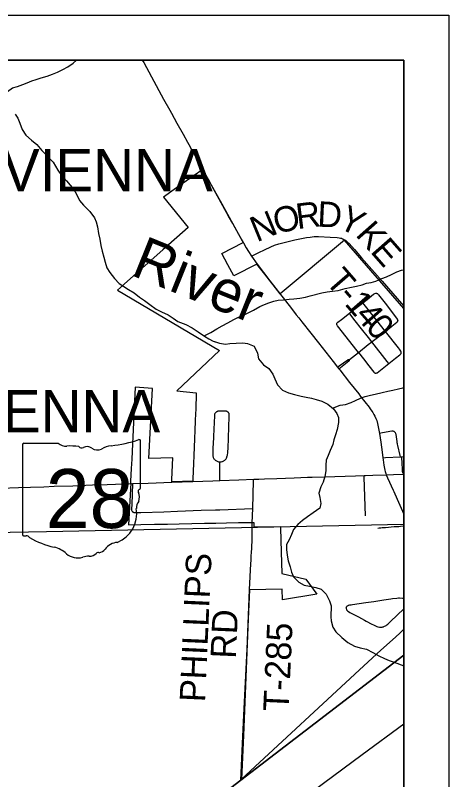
# Model space of a CAD drawing. Extents: x 0 to 48.6, y 0 to 22.
# Drawn here: x 8.031 to 9, y 19.291 to 21 of the extents above; entities that cross this region are included whole.
import ezdxf

# ---------------------------------------------------------------- set-up
doc = ezdxf.new("R2010")
doc.units = 0
for name, color, linetype in [('GM_X_City_Street', 7, 'Continuous'), ('GM_X_Corporation', 7, 'Continuous'), ('GM_X_Corporation_Text', 7, 'Continuous'), ('GM_X_Major_River', 7, 'Continuous'), ('GM_X_Major_River_Text', 7, 'Continuous'), ('GM_X_Minor_River', 7, 'Continuous'), ('GM_X_Rail_Line', 7, 'Continuous'), ('GM_X_State_Location', 7, 'Continuous'), ('GM_X_State_Route', 7, 'Continuous'), ('GM_X_State_Shield', 7, 'Continuous'), ('GM_X_Township_Road', 7, 'Continuous'), ('GM_X_Township_Road_Text', 7, 'Continuous'), ('SH_Data', 7, 'Continuous')]:
    doc.layers.add(name, color=color, linetype=linetype)

msp = doc.modelspace()

# ---------------------------------------------------------------- linework, layer by layer
at = {"layer": 'GM_X_City_Street'}
for points in [[(8.7982, 20.2463), (8.7953, 20.25), (8.7512, 20.3058), (8.7504, 20.307), (8.75, 20.3079), (8.7498, 20.3091), (8.7497, 20.3104), (8.75, 20.3114), (8.7506, 20.3124), (8.7521, 20.3141), (8.7601, 20.3199), (8.7781, 20.3338), (8.7837, 20.3381), (8.7919, 20.3447), (8.8079, 20.3571), (8.8174, 20.3645), (8.832, 20.3761), (8.835, 20.3779), (8.8367, 20.3784), (8.8377, 20.3784), (8.8384, 20.3784), (8.8396, 20.378), (8.8405, 20.3775), (8.8412, 20.3769), (8.8422, 20.3758), (8.8431, 20.3747), (8.8578, 20.356), (8.8746, 20.3345), (8.885, 20.3204), (8.8855, 20.3196), (8.8858, 20.3189), (8.886, 20.3183), (8.8861, 20.3173)], [(8.7982, 20.2463), (8.8093, 20.2319), (8.8214, 20.2162), (8.8325, 20.2023), (8.8335, 20.2012), (8.8343, 20.2005), (8.835, 20.2001), (8.8356, 20.1998), (8.8365, 20.1996), (8.838, 20.1998), (8.8391, 20.2002), (8.8399, 20.2008), (8.866, 20.2212), (8.8813, 20.2331), (8.8904, 20.2404), (8.8913, 20.2412), (8.8922, 20.242), (8.8929, 20.243), (8.8934, 20.244), (8.8937, 20.2456), (8.8935, 20.2472), (8.8929, 20.2487), (8.8916, 20.2508), (8.8896, 20.2537), (8.8874, 20.2565), (8.8586, 20.2931), (8.839, 20.3178), (8.8136, 20.3499), (8.8079, 20.3571)], [(8.866, 20.2212), (8.8624, 20.2259), (8.828, 20.2701), (8.8206, 20.2796), (8.8052, 20.2991), (8.7909, 20.3171), (8.7814, 20.3294), (8.7781, 20.3338)], [(8.7782, 20.2303), (8.7982, 20.2463), (8.8196, 20.2635), (8.828, 20.2701), (8.8289, 20.2707), (8.8526, 20.2887), (8.8586, 20.2931), (8.8731, 20.3048), (8.8841, 20.3137), (8.8852, 20.3148), (8.8857, 20.3154), (8.8859, 20.3161), (8.8861, 20.3173)], [(8.7515, 20.2133), (8.7553, 20.2161), (8.7742, 20.2299), (8.7748, 20.2302), (8.7756, 20.2304), (8.7767, 20.2306), (8.7782, 20.2303)], [(8.7545, 20.2095), (8.758, 20.2122), (8.777, 20.227), (8.7775, 20.2276), (8.7779, 20.2282), (8.7782, 20.2289), (8.7782, 20.2303)], [(8.4881, 19.9598), (8.4881, 19.9626), (8.4883, 20.0012), (8.4912, 20.0016), (8.4931, 20.0021), (8.4939, 20.0024), (8.4954, 20.0031), (8.4968, 20.0038), (8.4981, 20.0046), (8.499, 20.0052), (8.4998, 20.0059), (8.5007, 20.0066), (8.5014, 20.0073), (8.5021, 20.0083), (8.5028, 20.0094), (8.5033, 20.0102), (8.5038, 20.0115), (8.5042, 20.0124), (8.5048, 20.0147), (8.5053, 20.0165), (8.5056, 20.0182), (8.506, 20.0209), (8.5061, 20.0227), (8.5063, 20.0249), (8.5066, 20.0316), (8.5092, 20.1031), (8.5092, 20.1041), (8.5092, 20.1051), (8.5092, 20.1061), (8.509, 20.1075), (8.5087, 20.1092), (8.5083, 20.1101), (8.508, 20.1107), (8.5077, 20.1112), (8.5072, 20.1119), (8.5067, 20.1124), (8.5057, 20.1132), (8.5051, 20.1136), (8.5044, 20.114), (8.5038, 20.1143), (8.5032, 20.1145), (8.5015, 20.1147), (8.4993, 20.1148), (8.4917, 20.1147), (8.4902, 20.1147), (8.4878, 20.1146), (8.4863, 20.1146), (8.4852, 20.1145), (8.484, 20.1144), (8.4834, 20.1143), (8.4826, 20.1141), (8.4819, 20.1138), (8.4812, 20.1135), (8.4805, 20.1131), (8.4797, 20.1125), (8.4789, 20.1118), (8.4782, 20.1112), (8.4778, 20.1106), (8.4772, 20.1098), (8.4769, 20.1092), (8.4765, 20.1084), (8.4763, 20.1077), (8.4762, 20.1067), (8.4761, 20.106), (8.476, 20.1049), (8.4753, 20.0889), (8.4747, 20.0753), (8.4739, 20.0573), (8.4732, 20.0418), (8.4727, 20.0332), (8.4725, 20.0295), (8.4724, 20.0184), (8.4725, 20.0158), (8.4727, 20.0139), (8.473, 20.0123), (8.4735, 20.011), (8.4743, 20.0095), (8.4749, 20.0085), (8.4759, 20.0073), (8.4769, 20.0063), (8.478, 20.0053), (8.4795, 20.0042), (8.4807, 20.0034), (8.4821, 20.0026), (8.4838, 20.0019), (8.4851, 20.0016), (8.4865, 20.0013), (8.4883, 20.0012)], [(8.8919, 20.0127), (8.8912, 20.0155), (8.8862, 20.0377), (8.8855, 20.0408), (8.8852, 20.0422), (8.8849, 20.0434), (8.8847, 20.0446), (8.8844, 20.0469), (8.8822, 20.0624), (8.8819, 20.064), (8.8817, 20.0651), (8.8812, 20.0661), (8.8805, 20.0672), (8.8798, 20.0681), (8.8789, 20.0688), (8.8783, 20.0692), (8.8773, 20.0696), (8.876, 20.07), (8.8749, 20.0701), (8.873, 20.0702), (8.8687, 20.0695), (8.8485, 20.0656), (8.845, 20.065)], [(8.8526, 20.0106), (8.8586, 20.0109), (8.8919, 20.0127), (8.8951, 20.0129), (8.9, 20.0131)], [(8.9, 19.9734), (8.8997, 19.9738), (8.8982, 19.9757), (8.8974, 19.9774), (8.897, 19.9792), (8.8968, 19.9817), (8.8959, 20.0015), (8.8955, 20.0081), (8.8951, 20.0129)], [(8.814, 19.881), (8.811, 19.9668), (8.8109, 19.9708)], [(8.2932, 19.9529), (8.2912, 19.906), (8.2909, 19.8966), (8.2909, 19.8949), (8.291, 19.8936), (8.2913, 19.8924), (8.2919, 19.8911), (8.2924, 19.8904), (8.2931, 19.8897), (8.2936, 19.8894), (8.2942, 19.889), (8.2948, 19.8887), (8.296, 19.8884), (8.2969, 19.8882), (8.2979, 19.888), (8.2993, 19.8879), (8.302, 19.8878), (8.3051, 19.8878), (8.3113, 19.8879), (8.3627, 19.8899), (8.3932, 19.8909), (8.4466, 19.8931), (8.4784, 19.8939), (8.4885, 19.8942), (8.5617, 19.897)], [(8.8412, 19.8531), (8.8445, 19.8536), (8.8479, 19.8541), (8.8515, 19.8543), (8.859, 19.8549), (8.8781, 19.8566), (8.8816, 19.8568), (8.8843, 19.8569), (8.8884, 19.8572), (8.8923, 19.8574), (8.8994, 19.8581), (8.9, 19.8582)], [(8.7709, 19.6749), (8.7712, 19.6764), (8.7715, 19.6771), (8.7721, 19.6782), (8.7726, 19.6787), (8.7732, 19.6793), (8.774, 19.6798), (8.775, 19.6803), (8.7757, 19.6806), (8.7768, 19.6809), (8.7787, 19.6814), (8.7799, 19.6816), (8.782, 19.682), (8.7849, 19.6824), (8.815, 19.6866), (8.8328, 19.6894), (8.8549, 19.6929), (8.8705, 19.6953), (8.8745, 19.6958), (8.8841, 19.6969), (8.8877, 19.6971), (8.8903, 19.6971), (8.8967, 19.6966), (8.8985, 19.6963), (8.9, 19.696)], [(8.7709, 19.6749), (8.7709, 19.674), (8.7709, 19.6733), (8.7711, 19.6723), (8.7714, 19.6712), (8.7718, 19.6706), (8.7724, 19.6696), (8.7736, 19.6685), (8.7758, 19.6667), (8.7791, 19.6647), (8.7833, 19.6624), (8.7939, 19.6568), (8.7982, 19.6545), (8.8115, 19.6474), (8.8152, 19.6455), (8.8281, 19.6386), (8.8317, 19.6368), (8.8364, 19.6346), (8.8391, 19.6335), (8.8418, 19.6325), (8.8456, 19.6318), (8.8477, 19.6317), (8.8497, 19.6317), (8.8512, 19.6319), (8.8525, 19.6322), (8.8539, 19.6325), (8.8551, 19.633), (8.8567, 19.6337), (8.8587, 19.6348), (8.8599, 19.6356), (8.8618, 19.637), (8.8637, 19.6387), (8.8696, 19.6443), (8.9, 19.6729)]]:
    msp.add_lwpolyline(points, dxfattribs=at)
at = {"layer": 'GM_X_Corporation'}
msp.add_lwpolyline([(6.9471, 18.0777), (7.2261, 18.2847), (8.5348, 19.2897), (8.9, 19.5692), (8.9, 20.9), (2.1, 20.9)], dxfattribs=at)
for points in [[(8.9, 19.5692), (8.9, 20.9), (5.795, 20.9), (5.8236, 20.7829), (6.0412, 19.8859), (6.2759, 18.9159), (6.3396, 18.6531), (6.4996, 17.9212), (6.5365, 17.7727), (6.9471, 18.0777), (7.2261, 18.2847), (8.5348, 19.2897)], [(8.9, 19.6269), (8.9, 20.344), (8.7669, 20.4968), (8.6233, 20.3768), (8.5885, 20.4211), (8.571, 20.4438), (8.5195, 20.4173), (8.5061, 20.4419), (8.4924, 20.467), (8.5406, 20.4918), (8.5389, 20.4948), (8.517, 20.5345), (8.5079, 20.5508), (8.4498, 20.6551), (8.4285, 20.6401), (8.3914, 20.6138), (8.3619, 20.593), (8.4171, 20.5257), (8.3605, 20.4754), (8.2815, 20.4052), (8.2662, 20.3916), (8.2594, 20.3856), (8.4875, 20.2507), (8.3918, 20.1601), (8.4352, 20.156), (8.4343, 20.118), (8.4339, 20.1104), (8.4332, 20.0921), (8.4323, 20.0726), (8.4315, 20.053), (8.4307, 20.0343), (8.4299, 20.0153), (8.4292, 19.9974), (8.4277, 19.9633), (8.4275, 19.9583), (8.3805, 19.9568), (8.3807, 19.9616), (8.3833, 20.0102), (8.3297, 20.0088), (8.3374, 20.1651), (8.2991, 20.1687), (8.2928, 20.0418), (8.2912, 20.0077), (8.2901, 19.9865), (8.2887, 19.9583), (8.2885, 19.9537), (8.2892, 19.9537), (8.2843, 19.8606), (8.3119, 19.8611), (8.3422, 19.8618), (8.3709, 19.8623), (8.3971, 19.8628), (8.4256, 19.8634), (8.4541, 19.864), (8.4793, 19.8645), (8.5028, 19.8649), (8.5296, 19.8655), (8.5565, 19.866), (8.5641, 19.8655), (8.5642, 19.8603), (8.5643, 19.8561), (8.623, 19.8572), (8.6236, 19.8528), (8.6251, 19.8005), (8.6266, 19.7514), (8.6805, 19.739), (8.7054, 19.7054), (8.6283, 19.6925), (8.6276, 19.7168), (8.5546, 19.7155), (8.5519, 19.6502), (8.5411, 19.3898), (8.537, 19.2921), (8.8103, 19.5449), (8.8483, 19.5801), (8.8741, 19.6034), (8.8897, 19.6176)], [(5.0944, 14.1), (8.9, 14.1), (8.9, 19.5692), (8.5348, 19.2897), (7.2261, 18.2847), (6.9471, 18.0777), (6.5365, 17.7727), (5.8387, 17.2541), (5.5264, 17.0064), (4.6225, 16.3345), (4.044, 15.9033), (4.0346, 15.8959), (4.0398, 15.887), (4.3544, 15.3539), (4.4679, 15.1616), (4.7542, 14.6766)]]:
    msp.add_lwpolyline(points, close=True, dxfattribs=at)
at = {"layer": 'GM_X_Major_River'}
for points in [[(8.0307, 20.7792), (8.0366, 20.7697), (8.041, 20.7586), (8.0465, 20.7449), (8.0543, 20.7319), (8.0667, 20.7207), (8.079, 20.7107), (8.0899, 20.6977), (8.1153, 20.6715), (8.1257, 20.6539), (8.1323, 20.644), (8.145, 20.6298), (8.1536, 20.6202), (8.1615, 20.6106), (8.1678, 20.6003), (8.1744, 20.5862), (8.183, 20.5751), (8.1972, 20.5612), (8.2076, 20.5474), (8.212, 20.5379), (8.2146, 20.5269), (8.217, 20.5124), (8.2195, 20.4991), (8.222, 20.4854), (8.2248, 20.4725), (8.2288, 20.4588), (8.2317, 20.4481), (8.2357, 20.4355), (8.242, 20.4252), (8.2528, 20.4114), (8.2633, 20.4003), (8.2843, 20.3867), (8.2964, 20.3797), (8.3083, 20.3697), (8.32, 20.362), (8.3313, 20.3531), (8.3455, 20.3427), (8.3579, 20.3368), (8.3726, 20.3298), (8.3839, 20.3228), (8.3944, 20.3155), (8.4122, 20.3084), (8.4265, 20.3014), (8.44, 20.2925), (8.4539, 20.2825), (8.4637, 20.2763), (8.4735, 20.2712), (8.4874, 20.2665), (8.501, 20.2644), (8.5109, 20.2662), (8.5249, 20.2668), (8.5397, 20.2673), (8.5503, 20.2657), (8.5647, 20.2598), (8.5724, 20.2442), (8.5749, 20.2316), (8.5861, 20.2182), (8.5977, 20.2101)], [(8.5977, 20.2101), (8.6067, 20.1974), (8.6115, 20.1871), (8.6173, 20.1738), (8.6282, 20.1619), (8.6421, 20.1556), (8.655, 20.1517), (8.6697, 20.1484), (8.681, 20.146), (8.6931, 20.144), (8.7033, 20.1412), (8.7165, 20.1368), (8.7297, 20.1306), (8.7421, 20.1202), (8.7499, 20.1099), (8.7532, 20.1003), (8.7534, 20.0893), (8.7502, 20.0738), (8.747, 20.0617), (8.7431, 20.0504), (8.7406, 20.0402), (8.7352, 20.027), (8.7301, 20.0153), (8.7262, 20.0055), (8.7249, 19.9937), (8.7251, 19.9816), (8.723, 19.9683), (8.719, 19.9558), (8.714, 19.9453), (8.7092, 19.9313), (8.7121, 19.9214), (8.7139, 19.9085), (8.7118, 19.8979), (8.6969, 19.8871), (8.6839, 19.8785), (8.6728, 19.8699), (8.6628, 19.861), (8.6532, 19.8501), (8.6481, 19.8392), (8.6434, 19.8267), (8.6376, 19.8169), (8.637, 19.8052), (8.6391, 19.793), (8.6413, 19.7804), (8.6456, 19.7663), (8.6485, 19.7549), (8.6529, 19.7446), (8.6652, 19.732), (8.6765, 19.7257), (8.6886, 19.7233), (8.703, 19.7201), (8.7147, 19.7165), (8.7259, 19.7058), (8.7337, 19.6905), (8.737, 19.6798), (8.7366, 19.6552), (8.7373, 19.6457), (8.7412, 19.632), (8.7475, 19.6216), (8.761, 19.6089), (8.7741, 19.5974), (8.7896, 19.5892), (8.802, 19.5853), (8.8164, 19.5828), (8.8303, 19.5754), (8.8439, 19.5677), (8.8563, 19.5618), (8.8665, 19.5571), (8.8778, 19.5532)]]:
    msp.add_lwpolyline(points, dxfattribs=at)
at = {"layer": 'GM_X_Minor_River'}
msp.add_line((8.8778, 19.5532), (8.9, 19.5455), dxfattribs=at)
for points in [[(7.9905, 20.8065), (8.002, 20.8162), (8.0131, 20.8294), (8.0249, 20.8376), (8.0356, 20.8406), (8.0478, 20.845), (8.0577, 20.8487), (8.0679, 20.8532), (8.0778, 20.8565), (8.0885, 20.8598), (8.1022, 20.8639), (8.114, 20.868), (8.1254, 20.8728), (8.1369, 20.8791), (8.1483, 20.8847), (8.1601, 20.893), (8.1675, 20.9)], [(8.453, 20.2831), (8.4677, 20.2905), (8.4818, 20.2988), (8.4937, 20.3059), (8.5063, 20.3126), (8.5192, 20.32), (8.5299, 20.3249), (8.5413, 20.3293), (8.5531, 20.3357), (8.5634, 20.3405), (8.5779, 20.3487), (8.5882, 20.3536), (8.5977, 20.3573), (8.6088, 20.361), (8.619, 20.3628), (8.6308, 20.3638), (8.6429, 20.3649), (8.654, 20.3659), (8.6673, 20.3677), (8.6794, 20.3698), (8.6904, 20.3724), (8.7163, 20.379), (8.7285, 20.3819), (8.7403, 20.383), (8.7528, 20.3844), (8.7684, 20.3888), (8.7825, 20.3924), (8.7935, 20.3942), (8.8064, 20.3975), (8.8163, 20.4009), (8.8266, 20.4023), (8.8368, 20.4056), (8.8505, 20.4112), (8.8612, 20.4153), (8.8719, 20.4205), (8.8837, 20.4265), (8.8943, 20.4298), (8.9, 20.4311)], [(8.4763, 20.2703), (8.4874, 20.2665), (8.501, 20.2644), (8.5109, 20.2662), (8.5249, 20.2668), (8.5397, 20.2673), (8.5503, 20.2657), (8.5647, 20.2598), (8.5724, 20.2442), (8.5749, 20.2316), (8.5861, 20.2182), (8.5977, 20.2101)], [(8.5977, 20.2101), (8.6067, 20.1974), (8.6115, 20.1871), (8.6173, 20.1738), (8.6282, 20.1619), (8.6421, 20.1556), (8.655, 20.1517), (8.6697, 20.1484), (8.681, 20.146), (8.6931, 20.144), (8.7033, 20.1412), (8.7165, 20.1368), (8.7297, 20.1306), (8.7421, 20.1202), (8.7499, 20.1099), (8.7532, 20.1003), (8.7534, 20.0893), (8.7502, 20.0738), (8.747, 20.0617), (8.7431, 20.0504), (8.7406, 20.0402), (8.7352, 20.027), (8.7301, 20.0153), (8.7262, 20.0055), (8.7249, 19.9937), (8.7251, 19.9816), (8.723, 19.9683), (8.719, 19.9558), (8.714, 19.9453), (8.7092, 19.9313), (8.7121, 19.9214), (8.7139, 19.9085), (8.7118, 19.8979), (8.6969, 19.8871), (8.6839, 19.8785), (8.6728, 19.8699), (8.6628, 19.861), (8.6532, 19.8501), (8.6481, 19.8392), (8.6434, 19.8267), (8.6376, 19.8169), (8.637, 19.8052), (8.6391, 19.793), (8.6413, 19.7804), (8.6456, 19.7663), (8.6485, 19.7549), (8.6529, 19.7446), (8.6652, 19.732), (8.6765, 19.7257), (8.6886, 19.7233), (8.703, 19.7201), (8.7147, 19.7165), (8.7259, 19.7058), (8.7337, 19.6905), (8.737, 19.6798), (8.7366, 19.6552), (8.7373, 19.6457), (8.7412, 19.632), (8.7475, 19.6216), (8.761, 19.6089), (8.7741, 19.5974), (8.7896, 19.5892), (8.802, 19.5853), (8.8164, 19.5828), (8.8303, 19.5754), (8.8439, 19.5677), (8.8563, 19.5618), (8.8665, 19.5571), (8.8778, 19.5532)], [(8.7402, 20.1218), (8.7573, 20.1278), (8.7695, 20.1299), (8.782, 20.134), (8.7916, 20.1385), (8.803, 20.144), (8.8129, 20.1474), (8.825, 20.1503), (8.8357, 20.1525), (8.8509, 20.1565), (8.8638, 20.1594), (8.8749, 20.1616), (8.8878, 20.1649), (8.8977, 20.1671), (8.9, 20.1675)]]:
    msp.add_lwpolyline(points, dxfattribs=at)
at = {"layer": 'GM_X_Rail_Line'}
msp.add_lwpolyline([(2.1, 19.7643), (2.1011, 19.7645), (2.172, 19.7738), (2.2311, 19.7779), (2.3038, 19.7803), (2.4027, 19.7791), (2.7583, 19.782), (3.4579, 19.785), (4.2295, 19.785), (4.6206, 19.7852), (5.0462, 19.7937), (5.6922, 19.8043), (6.0216, 19.8102), (6.7352, 19.82), (7.2096, 19.8291), (8.1004, 19.8459), (8.9, 19.8619)], dxfattribs=at)
at = {"layer": 'GM_X_State_Route'}
for p, q in [((8.5588, 20.4616), (8.5714, 20.4433)), ((8.7515, 20.2133), (8.7545, 20.2095))]:
    msp.add_line(p, q, dxfattribs=at)
for points in [[(8.3148, 20.9), (8.3179, 20.8942), (8.3356, 20.8621), (8.3625, 20.8124), (8.3763, 20.7877), (8.3799, 20.7813), (8.3924, 20.7587), (8.4059, 20.734), (8.4157, 20.7162), (8.4188, 20.7108), (8.4274, 20.6954), (8.431, 20.6891), (8.437, 20.6782), (8.4405, 20.672), (8.4503, 20.6547), (8.4572, 20.6417), (8.465, 20.6276), (8.4925, 20.5783), (8.5091, 20.5484), (8.5299, 20.5109), (8.5409, 20.4911), (8.5472, 20.4802), (8.5525, 20.4716), (8.5588, 20.4616)], [(8.5714, 20.4433), (8.5998, 20.4062), (8.6482, 20.3447), (8.6592, 20.3305), (8.6645, 20.3237), (8.6718, 20.3142), (8.6915, 20.2895), (8.7089, 20.2676), (8.7415, 20.226), (8.7515, 20.2133)], [(8.7545, 20.2095), (8.7565, 20.207), (8.7784, 20.1792), (8.7989, 20.1534), (8.8031, 20.1479)], [(8.8031, 20.1479), (8.8219, 20.1235), (8.8245, 20.1201), (8.8283, 20.1147), (8.8304, 20.1114), (8.8329, 20.1073), (8.8347, 20.1038), (8.8374, 20.0983), (8.8391, 20.0936), (8.8408, 20.0869), (8.845, 20.065)], [(8.845, 20.065), (8.8481, 20.0452), (8.8509, 20.023), (8.8526, 20.0106)], [(8.8526, 20.0106), (8.8532, 20.0058), (8.8549, 19.9943), (8.8557, 19.99), (8.8572, 19.9831), (8.858, 19.9799), (8.8592, 19.9757), (8.8602, 19.9723)], [(8.5752, 19.9629), (8.5877, 19.9634), (8.6157, 19.9641), (8.6541, 19.9658), (8.6845, 19.967), (8.6947, 19.9673)], [(8.6947, 19.9673), (8.7224, 19.9682), (8.7913, 19.9703), (8.8109, 19.9708), (8.8142, 19.9709), (8.8304, 19.9714), (8.8602, 19.9723)], [(8.8602, 19.9723), (8.8769, 19.9728), (8.8997, 19.9738), (8.9, 19.9738)], [(8.8602, 19.9723), (8.8631, 19.9659), (8.8758, 19.9382), (8.8772, 19.935), (8.8848, 19.9182), (8.9, 19.8846)], [(7.9981, 19.9429), (8.0378, 19.9444), (8.0651, 19.9451), (8.0949, 19.9459), (8.1178, 19.9467), (8.1594, 19.9481), (8.2036, 19.9498), (8.2363, 19.9509), (8.2932, 19.9529)], [(8.2932, 19.9529), (8.328, 19.954), (8.3806, 19.9558), (8.4281, 19.9577), (8.4723, 19.9593), (8.4881, 19.9598), (8.5306, 19.9613), (8.564, 19.9625), (8.5704, 19.9627), (8.5752, 19.9629)]]:
    msp.add_lwpolyline(points, dxfattribs=at)
at = {"layer": 'GM_X_State_Shield'}
for p, q in [((8.047, 20.0394), (8.047, 19.8393)), ((8.1268, 20.0428), (8.0496, 20.0428)), ((8.3107, 19.9431), (8.3107, 20.0478)), ((8.3107, 19.9431), (8.3107, 19.9431))]:
    msp.add_line(p, q, dxfattribs=at)
for centre, radius, start, end in [((8.2168, 20.3157), 0.2796, 275.8445, 288.9065), ((8.3078, 20.0482), 0.00294, 351.8621, 97.738), ((8.0501, 20.0398), 0.00305, 98.1301, 188.1301), ((8.1452, 20.0661), 0.0296, 231.6195, 271.1119), ((8.1551, 19.9305), 0.1064, 80.4867, 94.9883), ((8.1792, 20.0409), 0.00855, 219.7921, 297.1024), ((8.1917, 20.0177), 0.0178, 54.4667, 119.1411), ((8.2524, 19.9817), 0.0563, 97.3462, 120.7689), ((8.2147, 20.0494), 0.0214, 233.8562, 294.8282), ((8.31, 19.9354), 0.00454, 107.944, 210.337), ((8.2811, 19.9222), 0.0273, 340.033, 23.6496), ((8.3076, 19.9427), 0.00314, 289.6038, 7.7341), ((8.3212, 19.8993), 0.0198, 136.8065, 186.9296), ((8.2324, 19.886), 0.0699, 292.3089, 8.9858), ((8.0501, 19.8388), 0.00308, 171.9584, 258.3066), ((8.0505, 19.8593), 0.0235, 267.339, 280.6039), ((8.0554, 19.8277), 0.00848, 29.7484, 93.2717), ((8.1624, 20.0075), 0.2019, 240.4129, 257.1985), ((8.2619, 19.7831), 0.0383, 94.4031, 142.5768), ((8.1022, 19.7494), 0.0632, 47.1842, 75.836), ((8.1705, 19.8267), 0.0401, 230.7004, 286.2918), ((8.1966, 19.8117), 0.0214, 268.777, 315.5493), ((8.216, 19.7924), 0.00601, 65.7517, 132.6484), ((8.2134, 19.8199), 0.0226, 282.8732, 323.2771), ((8.1937, 19.7575), 0.0329, 85.6951, 111.2099)]:
    msp.add_arc(centre, radius, start, end, dxfattribs=at)
at = {"layer": 'GM_X_Township_Road'}
for p, q in [((8.5606, 19.8652), (8.5617, 19.897)), ((8.5607, 19.8533), (8.5606, 19.8652))]:
    msp.add_line(p, q, dxfattribs=at)
for points in [[(8.5588, 20.4616), (8.5755, 20.4694), (8.5884, 20.4756), (8.6024, 20.4823), (8.6104, 20.4856), (8.6198, 20.4889), (8.6318, 20.4922), (8.656, 20.4977), (8.6822, 20.503), (8.6902, 20.5042), (8.6989, 20.505), (8.7088, 20.505), (8.7349, 20.5041), (8.7504, 20.5032), (8.7552, 20.5025), (8.7582, 20.5019), (8.7603, 20.5013), (8.7628, 20.5003), (8.7647, 20.4995), (8.7673, 20.4981), (8.769, 20.4971), (8.7708, 20.4957), (8.7723, 20.4945), (8.7739, 20.493), (8.7773, 20.4896), (8.7892, 20.476), (8.805, 20.4577), (8.8337, 20.425), (8.851, 20.4054), (8.875, 20.3777), (8.9, 20.3492)], [(8.5617, 19.897), (8.5638, 19.9586), (8.564, 19.9625)], [(8.5543, 19.7149), (8.5544, 19.7159), (8.5576, 19.7733), (8.558, 19.7814), (8.5586, 19.7913), (8.559, 19.7985), (8.5594, 19.8083), (8.5602, 19.8287), (8.5607, 19.8533)], [(8.535, 19.2892), (8.5379, 19.3551), (8.5421, 19.4351), (8.549, 19.5829), (8.5543, 19.7149)], [(8.5423, 19.1723), (8.5498, 19.1679), (8.555, 19.1655), (8.5649, 19.1671), (8.5704, 19.1715), (8.8068, 19.3467), (8.9, 19.4153)]]:
    msp.add_lwpolyline(points, dxfattribs=at)
at = {"layer": 'SH_Data'}
for p, q in [((2, 21), (9, 21)), ((9, 21), (9, 14)), ((2.1, 20.9), (8.9, 20.9)), ((8.9, 20.9), (8.9, 14.1))]:
    msp.add_line(p, q, dxfattribs=at)

# ---------------------------------------------------------------- texts
at = {"layer": 'GM_X_Corporation_Text'}
for p in [(7.6702, 20.606), (7.5527, 20.0671)]:
    msp.add_text('NEW VIENNA', height=0.0947, rotation=0, dxfattribs=at).set_placement(p)
at = {"layer": 'GM_X_Major_River_Text'}
msp.add_text('River', height=0.0947, rotation=338.1059, dxfattribs=at).set_placement((8.2864, 20.42))
at = {"layer": 'GM_X_State_Location'}
for s in ['s', 'r']:
    msp.add_text(s, height=0.000189, dxfattribs=at).set_placement((8.1759, 19.926))
msp.add_text('28', height=0.000189, rotation=0, dxfattribs=at).set_placement((8.1282, 19.9122))
at = {"layer": 'GM_X_State_Shield'}
msp.add_text('28', height=0.13184, dxfattribs=at).set_placement((8.0988, 19.8534))
at = {"layer": 'GM_X_Township_Road_Text'}
for s, height, rotation, p in [('R', 0.0568, 7.1023, (8.6617, 20.5218)), ('D', 0.0568, 357.3726, (8.7055, 20.5275)), ('O', 0.0568, 13.5715, (8.6148, 20.5104)), ('Y', 0.0568, 334.1453, (8.7496, 20.5266)), ('N', 0.0568, 22.4055, (8.5708, 20.492)), ('K', 0.0568, 311.4611, (8.7899, 20.5084)), ('E', 0.0568, 311.2791, (8.8229, 20.471)), ('T', 0.0568, 310.9602, (8.7221, 20.404)), ('-', 0.0568, 310.9848, (8.7499, 20.3719)), ('1', 0.0568, 311.0199, (8.7653, 20.3542)), ('4', 0.0568, 311.2012, (8.7884, 20.3277)), ('0', 0.0568, 311.8431, (8.8119, 20.3008)), ('PHILLIPS', 0.05682, 87.4332, (8.455, 19.4634)), ('RD', 0.05682, 87.5314, (8.5241, 19.5606)), ('T-285', 0.05682, 87.366, (8.6418, 19.4424))]:
    msp.add_text(s, height=height, rotation=rotation, dxfattribs=at).set_placement(p)

doc.saveas('drawing.dxf')
